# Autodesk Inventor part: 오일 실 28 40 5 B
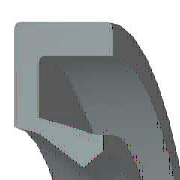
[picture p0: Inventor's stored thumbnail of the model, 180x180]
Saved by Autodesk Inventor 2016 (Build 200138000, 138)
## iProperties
IsCustomPart: 1
Created: 2012-02
Part Number: 오일 실 28 40 5 B
Material: 고무
Description: 오일 실 - 비스프링, 조립 GA
Document SubType Name: Modeling
Standard: JIS B 2402
Designer: mduedu
Standards Organization: JIS
Language: ko-KR
Size Designation: 28 40 5 B
Categories: <MemberInstance><Categories><Category DisplayName="샤프트 부품" InternalName="7f7aeb1f-a693-4053-b835-cee3144e0d98" Mnemonic="SHFT"><Category DisplayName="실링" Intern
Density: 0.93 g/cm^3
Appearance: Rubber-Black
Author: mduedu
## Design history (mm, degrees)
body "Solid1"
revolve "회전1" stored, may be unused: angle "d27" = 360 deg
fillet "모깎기1" dims "d28" = 0.25 (= 0.05 x b)
sketch "스케치2"
  geometry: L1 (15.971, -3.75)-(16.571, -5); L2 (15.171, -3.438)-(15.971, -3.75); L3 (14, -1.375)-(15.171, -3.438); L4 (14.923, -0.75)-(14, -1.375); L5 (17.6, -4.375)-(14.923, -0.75); L6 (17.6, -0.25)-(17.6, -4.375); L7 (18.8, -0.25)-(17.6, -0.25); L8 (18.8, 0)-(18.8, -0.25); L9 (20, 0)-(18.8, 0); L10 (20, -5)-(20, 0); L11 (16.571, -5)-(20, -5); L12 (0, -9.6)-(0, 1.6) reference; L13 (28, 0)-(14, 0) reference
  constraints: 22 end point, 3 horizontal, 3 vertical
  dimensions: "d2" = 5 distance of L10.start L9.start (= b); "d4" = 1.2 distance of L9.start L8.start (= 0.1 x dd - 0.1 x Diam); "d6" = 0.25 distance of L8.start L7.start (= 0.05 x b); "d8" = 0.92308 horizontal distance of L4.start L3.start (= 0.0769231 x dd - 0.0769231 x Diam); "d10" = 0.625 vertical distance of L5.start L10.start (= 0.125 x b); "d12" = 1.2 distance of L7.start L6.start (= 0.1 x dd - 0.1 x Diam); "d14" = 0.5 vertical distance of L4.start L6.start (= 0.1 x b); "d16" = 3.42857 distance of L1.end L10.start (= 0.285714 x dd - 0.285714 x Diam); "d18" = 0.6 horizontal distance of L1.start L1.end (= 0.05 x dd - 0.05 x Diam); "d20" = 0.625 vertical distance of L4.start L3.start (= 0.125 x b); "d22" = 1.25 vertical distance of L1.start L1.end (= 0.25 x b); "d24" = 0.8 horizontal distance of L2.start L1.start (= 0.0666667 x dd - 0.0666667 x Diam); "d26" = 0.3125 vertical distance of L2.start L1.start (= 0.0625 x b); "d29" = 0 distance between parallel lines of L13 L9; "d30" = 14 distance from line of L3.start L12 (= 0.5 x Diam); "d31" = 20 distance between parallel lines of L12 L10 (= 0.5 x dd)
other parameters: "Diam" = 28 [user parameter; used in 7 equation terms], "b" = 5 [user parameter; used in 8 equation terms], "d1" = 8 (derived), "d3" = 2 (derived), "d5" = 0.4 (derived), "d7" = 1.53846 (derived), "d9" = 1 (derived), "d11" = 2 (derived), "d13" = 0.8 (derived), "d15" = 5.71429 (derived), "d17" = 1 (derived), "d19" = 1 (derived), "d21" = 2 (derived), "d23" = 1.33333 (derived), "d25" = 0.5 (derived), "d32" = 0
